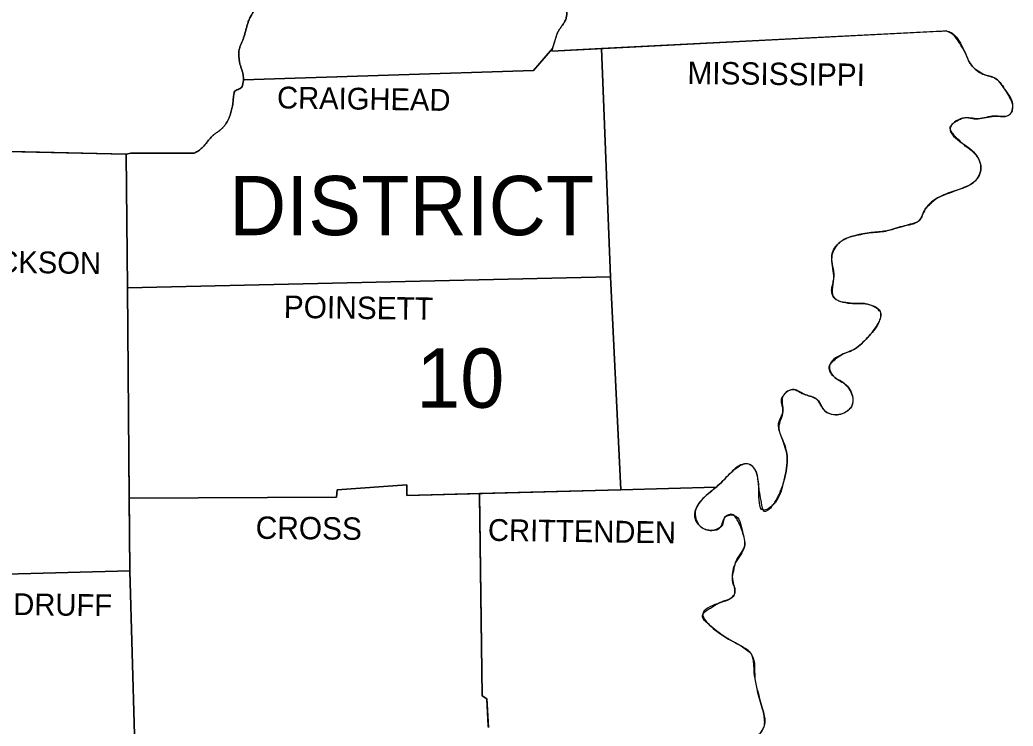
# Model space of a CAD drawing. Extents: x -28335 to 1228743, y -22428 to 152440.
# Drawn here: x 33552 to 37883, y 12977 to 16055 of the extents above; entities that cross this region are included whole.
import ezdxf

# ---------------------------------------------------------------- set-up
doc = ezdxf.new("R2010")
doc.units = 0
doc.layers.add('Level 16', color=7, linetype='Continuous')
doc.layers.add('Level 8', color=7, linetype='Continuous')

msp = doc.modelspace()

# ---------------------------------------------------------------- linework, layer by layer
at = {"layer": 'Level 16'}
for p, q in [((35874.9, 15930.7), (35895.4, 15993.9)), ((35871, 15918.7), (35874.9, 15930.7)), ((36087.9, 15929.9), (35871, 15918.7)), ((36127, 14935.6), (36087.9, 15929.9)), ((34015.7, 15470.2), (34020.8, 14887.6)), ((34020.8, 14887.6), (36127, 14935.6)), ((36127, 14935.6), (34020.8, 14887.6)), ((36173, 14007.6), (36127, 14935.6)), ((34020.8, 14887.6), (34028.8, 13970.5)), ((35556, 13990.7), (35556.1, 13981.9)), ((35556.1, 13981.9), (35556, 13990.7)), ((36173, 14007.6), (36588.4, 14019)), ((34028.8, 13970.5), (34031.6, 13653.5)), ((35556.1, 13981.9), (35567.5, 13109.8)), ((35567.5, 13109.8), (35556.1, 13981.9)), ((34031.6, 13653.5), (34051.1, 12939.8)), ((34051.1, 12939.8), (34031.6, 13653.5)), ((35567.5, 13109.8), (35587.8, 13096.2)), ((35587.8, 13096.2), (35567.5, 13109.8)), ((35587.8, 13096.2), (35594.6, 12978.4)), ((35594.6, 12978.4), (35587.8, 13096.2)), ((35594.6, 12978.4), (35595.1, 12970.9)), ((35595.1, 12970.9), (35594.6, 12978.4))]:
    msp.add_line(p, q, dxfattribs=at)
for points in [[(33330.1, 16791), (33331.6, 16743.3), (33139.1, 16725.2), (33141.3, 16661.7), (33082.4, 16659.5), (33102.8, 15490.6), (34015.7, 15470.2)], [(37590.4, 16007.1), (37575.9, 16006.3), (36087.9, 15929.9)], [(34526.7, 15793.9), (35791.7, 15834.9), (35874.9, 15930.7)], [(35874.9, 15930.7), (35791.7, 15834.9), (34526.7, 15793.9)], [(36087.9, 15929.9), (36127, 14935.6), (36173, 14007.6)], [(33424, 13957), (33435.8, 13637.6), (34031.6, 13653.5), (34028.8, 13970.5), (34020.8, 14887.6), (34015.7, 15470.2), (33512, 15481.5)], [(34015.7, 15470.2), (34036.1, 15474.7), (34312.5, 15474.7)], [(34312.5, 15474.7), (34036.1, 15474.7), (34015.7, 15470.2)], [(34028.8, 13970.5), (34933.2, 13975.2), (34935.4, 14006.9), (35239, 14029.5), (35239, 13981.9), (36173, 14007.6)], [(35556, 13990.7), (35239, 13981.9), (35239, 14029.5), (34935.4, 14006.9), (34933.2, 13975.2), (34028.8, 13970.5)], [(36588.4, 14019), (36173, 14007.6), (35556, 13990.7)], [(36588.4, 14019), (36588.4, 14019)], [(36588.4, 14019), (36588.4, 14019)], [(34031.6, 13653.5), (33435.8, 13637.6), (33424, 13957)]]:
    msp.add_lwpolyline(points, dxfattribs=at)
for points in [[(35895.4, 15993.9), (35898.2, 16002.5), (35906.5, 16016.1), (35915.8, 16029.4), (35924.8, 16042.9), (35932.2, 16056.9), (35936.2, 16073.4), (35937.3, 16091.1), (35938.6, 16108.6), (35943.5, 16124.9), (35955.2, 16143.2), (35969.2, 16160.2), (35983.4, 16177.2), (35995.6, 16195.1), (36002.3, 16210.4), (36007.7, 16226.6), (36013.8, 16242.3), (36022.8, 16256.3), (36077.1, 16317.4), (36117.9, 16362.7), (36130.6, 16375.5), (36144.1, 16387.5), (36157.5, 16399.6), (36170, 16412.6), (36175.1, 16420.1), (36178.5, 16428.5), (36182.4, 16447), (36185.7, 16465.8), (36192.7, 16482.8), (36203.7, 16499.3), (36215.1, 16515.5), (36227.2, 16531.2), (36240.2, 16546.2), (36251.8, 16558.8)], [(34513.6, 15756.7), (34514.1, 15757), (34520.9, 15764.7), (34522.9, 15771.1), (34524.5, 15777.6), (34526.5, 15790.7), (34526.8, 15803.9), (34525.4, 15816.8), (34521.9, 15830.9), (34517.2, 15845), (34512.7, 15859.2), (34509.6, 15873.4), (34507.8, 15887.5), (34506.7, 15901.8), (34507, 15916.1), (34509.6, 15930.1), (34514.2, 15943.8), (34519.6, 15957.3), (34525.1, 15970.8), (34529.9, 15984.4), (34534.6, 16000.2), (34538.9, 16016.1), (34543.3, 16032.1), (34548.1, 16047.9), (34554.9, 16064.1), (34563.6, 16079.7), (34572.4, 16095.3), (34576.2, 16102.7)], [(34576.2, 16102.7), (34572.4, 16095.3), (34563.6, 16079.7), (34554.9, 16064.1), (34548.1, 16047.9), (34543.3, 16032.1), (34538.9, 16016.1), (34534.6, 16000.2), (34529.9, 15984.4), (34525.1, 15970.8), (34519.6, 15957.3), (34514.2, 15943.8), (34509.6, 15930.1), (34507, 15916.1), (34506.7, 15901.8), (34507.8, 15887.5), (34509.6, 15873.4), (34512.7, 15859.2), (34517.2, 15845), (34521.9, 15830.9), (34525.4, 15816.8), (34526.8, 15803.9), (34526.7, 15793.9)], [(37356.2, 15142.3), (37400.1, 15155.3), (37435.5, 15165.7), (37470.3, 15178), (37480.8, 15187.4), (37486.9, 15201.5), (37492, 15216.9), (37499.8, 15230.1), (37514.1, 15245.5), (37529, 15260.6), (37563.2, 15284.5), (37598.2, 15298.3), (37633.4, 15311.6), (37669.8, 15326.1), (37705.9, 15343.4), (37719.9, 15354.7), (37730.5, 15369.4), (37742.1, 15402.3), (37742.8, 15417.6), (37739.9, 15433.6), (37733.5, 15449.3), (37724, 15463.4), (37708.2, 15479.2), (37691.5, 15492.6), (37674.6, 15505.5), (37658.3, 15520), (37627.6, 15550.5), (37615.1, 15566), (37608.5, 15581.2), (37608.3, 15584.6), (37608.9, 15587.9), (37612.3, 15594.6), (37625.6, 15607.3), (37644, 15618.3), (37662.9, 15626.5), (37671.4, 15628.6), (37679.9, 15629.2), (37696.9, 15627.3), (37713.9, 15624.4), (37730.8, 15624.3), (37765.9, 15629.9), (37801, 15635.6), (37816.8, 15635.9), (37832.7, 15634.4), (37848.7, 15634.7), (37864.5, 15640.1), (37867.5, 15642.1), (37870.3, 15644.5), (37875, 15649.9), (37880.9, 15662.9), (37880.3, 15689.9), (37867.8, 15718.4), (37850.9, 15746.6), (37831.2, 15774.6), (37807.8, 15798.7), (37794.7, 15805.9), (37780, 15809.9), (37765.2, 15813.4), (37751.2, 15819.1), (37701.4, 15857.6), (37691.1, 15873.6), (37683.6, 15890.9), (37676.5, 15908.6), (37667.4, 15925.5), (37651.5, 15950.7), (37634.7, 15975.5), (37615, 15995.8), (37590.4, 16007.1)], [(34526.7, 15793.9), (34526.5, 15790.7), (34524.5, 15777.6), (34522.9, 15771.1), (34520.9, 15764.7), (34514.1, 15757), (34513.6, 15756.7)], [(34312.5, 15474.7), (34321.9, 15479.6), (34330.6, 15484.8), (34346.5, 15497.4), (34358.4, 15510.1), (34369.3, 15523.5), (34380.2, 15536.9), (34391.8, 15549.5), (34402.2, 15558.2), (34413.3, 15566.2), (34424.5, 15574.3), (34434.8, 15583.5), (34443.8, 15593.8), (34451.7, 15604.7), (34464.3, 15628.8), (34471.9, 15651.3), (34477.8, 15674.1), (34480.8, 15690.4), (34482.3, 15707), (34483.9, 15723.6), (34485.1, 15731.7), (34486.9, 15739.8), (34493, 15747.5), (34503.5, 15752.2), (34513.6, 15756.7)], [(34513.6, 15756.7), (34503.5, 15752.2), (34493, 15747.5), (34486.9, 15739.8), (34485.1, 15731.7), (34483.9, 15723.6), (34482.3, 15707), (34480.8, 15690.4), (34477.8, 15674.1), (34471.9, 15651.3), (34464.3, 15628.8), (34451.7, 15604.7), (34443.8, 15593.8), (34434.8, 15583.5), (34424.5, 15574.3), (34413.3, 15566.2), (34402.2, 15558.2), (34391.8, 15549.5), (34380.2, 15536.9), (34369.3, 15523.5), (34358.4, 15510.1), (34346.5, 15497.4), (34330.6, 15484.8), (34321.9, 15479.6), (34312.5, 15474.7)], [(36968.6, 14425.1), (36971.9, 14423.7), (37021.8, 14405.5), (37034.7, 14394.6), (37043.6, 14378.8), (37052.4, 14362.2), (37064.8, 14348.9), (37093.8, 14336.3), (37123.7, 14335.3), (37152.6, 14346.5), (37165.9, 14356.3), (37178.1, 14369.3), (37182.6, 14416.9), (37148.6, 14469), (37137.5, 14478), (37125, 14484.8), (37112.5, 14491.7), (37101.1, 14500.7), (37084.5, 14524.3), (37082.9, 14548.3), (37092.5, 14561.7), (37105, 14574.2), (37135, 14595.8), (37149.3, 14602.7), (37163.9, 14608), (37178.2, 14613.4), (37191.7, 14620.7), (37248.3, 14670.6), (37261.7, 14685.6), (37273.8, 14701.3), (37295.9, 14734), (37306.9, 14759), (37307.7, 14772.1), (37302.7, 14783.8), (37296.3, 14790.8), (37289.3, 14796.9), (37273.8, 14806.5), (37239.2, 14817.8), (37222.9, 14819.5), (37206.4, 14819.2), (37189.9, 14818.8), (37173.6, 14820.1), (37152.9, 14822.9), (37132.3, 14826.6), (37113.6, 14834.4), (37098.8, 14849.5), (37095.9, 14855), (37093.9, 14860.5), (37091.9, 14871.5), (37093.9, 14893.6), (37098.9, 14915.8), (37101.1, 14937.9), (37098.9, 14958.8), (37095.7, 14979.8), (37093, 15000.8), (37092, 15021.7), (37094.2, 15037.7), (37100, 15053), (37121.5, 15080.6), (37129.7, 15087.5), (37138.1, 15093.5), (37155.2, 15102.9), (37173, 15109.6), (37191.7, 15114.6), (37227.8, 15122.1), (37264.2, 15128.2), (37280, 15129.8), (37296, 15130.9), (37327.6, 15135), (37356.2, 15142.3)], [(36588.4, 14019), (36602.7, 14031.8), (36654.8, 14083.9), (36677.7, 14102.4), (36690, 14110.4), (36702.4, 14117.9), (36720.4, 14122), (36738.6, 14115.6), (36748.4, 14106.8), (36756.3, 14097.1), (36762.2, 14086.4), (36765.8, 14074.8), (36768.6, 14057.3), (36770.6, 14039.7), (36774.9, 14004.6), (36782.3, 13960.9), (36793, 13918.5), (36796.1, 13914.3), (36801, 13913.5), (36814.1, 13919.3), (36838.3, 13943.4), (36849.8, 13962.7), (36860.3, 13982.1), (36869.4, 14002), (36876.8, 14022.7), (36894.9, 14099.7), (36897.2, 14154.1), (36876.8, 14226.6), (36860.9, 14278.7), (36860.7, 14296.1), (36866.3, 14313.7), (36873.8, 14331.3), (36879.1, 14348.9), (36879.4, 14356.9), (36878.2, 14365.1), (36874.3, 14381.6), (36872.7, 14398.2), (36879.1, 14414.6), (36884.6, 14421.6), (36890.4, 14428), (36902.8, 14438.5), (36928.9, 14444.1), (36948.7, 14435.2), (36968.6, 14425.1)], [(36702.4, 13825.6), (36687.6, 13862.9), (36677.8, 13880.1), (36672.2, 13888.2), (36666.1, 13895.9), (36657.8, 13900.2), (36647.1, 13899.4), (36636.3, 13895.1), (36627.6, 13889.1), (36621.7, 13878.9), (36618.9, 13866.2), (36615.4, 13853.6), (36607.2, 13843.8), (36597.6, 13838.2), (36588, 13833.9), (36578.3, 13831.2), (36568.7, 13830.2), (36556.2, 13830.8), (36543.8, 13833.5), (36531.3, 13839), (36518.9, 13848.3), (36514.8, 13852.3), (36511.1, 13856.5), (36504.8, 13865.2), (36496.7, 13883.4), (36494.7, 13901.7), (36498.5, 13918.5), (36505.7, 13933.4), (36514.5, 13948.1), (36537, 13975.2), (36562.7, 13997.6), (36588.4, 14019)], [(36332.9, 12569.7), (36360.3, 12573.1), (36387.5, 12579.8), (36392.4, 12582.1), (36396.9, 12584.8), (36405.1, 12591.5), (36418.3, 12608.2), (36428.6, 12627.8), (36437.3, 12647.7), (36462.2, 12706.6), (36487.2, 12761), (36521.1, 12824.4), (36555.1, 12887.8), (36574.9, 12914.9), (36602.7, 12933.1), (36609.9, 12935), (36617.2, 12935.8), (36632.2, 12934.9), (36661.6, 12928.6), (36674.1, 12925), (36686.5, 12920.3), (36699, 12915.8), (36711.4, 12912.8), (36723.3, 12912.1), (36735.2, 12914), (36747.1, 12918.7), (36759, 12926.3), (36768, 12933.9), (36776.1, 12941.7), (36789.1, 12958), (36797.2, 12975.5), (36799.8, 12994.3), (36798.8, 13008.5), (36796.9, 13022.7), (36790.7, 13050.9), (36768.1, 13132.5), (36762.1, 13161.9), (36756.7, 13191.4), (36754.1, 13214.5), (36752.9, 13237.9), (36750.9, 13261.2), (36745.4, 13284.3), (36742.4, 13290.9), (36738.2, 13296.7), (36727.6, 13306.7), (36702.4, 13322.8), (36685.4, 13332.7), (36668.3, 13342), (36651.2, 13351.3), (36634.4, 13361.3), (36599.9, 13384.9), (36566.5, 13411.1), (36537.6, 13438.3), (36528.7, 13452.9), (36530.2, 13465.5), (36535.9, 13471.8), (36542.7, 13477.8), (36558.6, 13489.3), (36576.3, 13500.1), (36593.6, 13510.8), (36602.7, 13515.7), (36612.2, 13519.5), (36631.5, 13526), (36650.1, 13534.5), (36666.1, 13549.3), (36668.7, 13553.5), (36670.4, 13557.7), (36671.5, 13566.3), (36667.7, 13584), (36661.4, 13601.9), (36659.3, 13619.5), (36664.7, 13654.7), (36672.9, 13689.7), (36681.4, 13708.1), (36693.1, 13725.2), (36704.4, 13742.1), (36711.4, 13760), (36702.4, 13825.6)]]:
    msp.add_spline(points, degree=3, dxfattribs=at)
at = {"layer": 'Level 8'}
msp.add_line((35871, 15918.7), (35895.4, 15993.9), dxfattribs=at)
for points in [[(32948.3, 17620.6), (32939.7, 17552), (32985, 17545.2), (32982.7, 17518), (33034.8, 17506.7), (33039.4, 17470.4), (33064.3, 17454.6), (33071.1, 17345.8), (33200.2, 17332.2), (33200.2, 17234.8), (33247.8, 17228), (33247.8, 17189.5), (33288.6, 17178.2), (33286.3, 17046.8), (33322.5, 17040), (33331.6, 16743.3), (33139.1, 16725.2), (33141.3, 16661.7), (33082.4, 16659.5), (33102.8, 15490.6), (34015.7, 15470.2), (34031.6, 13653.5), (33435.8, 13637.6), (33424, 13957)], [(35871, 15918.7), (37590.4, 16007.1)], [(34526.7, 15793.9), (35791.7, 15834.9), (35874.9, 15930.7)], [(36087.9, 15929.9), (36127, 14935.6), (36173, 14007.6)], [(34312.5, 15474.7), (34036.1, 15474.7), (34015.7, 15470.2)], [(36127, 14935.6), (34020.8, 14887.6)], [(34028.8, 13970.5), (34933.2, 13975.2), (34935.4, 14006.9), (35239, 14029.5), (35239, 13981.9), (36588.4, 14019)], [(35556, 13990.7), (35567.5, 13109.8), (35587.8, 13096.2), (35595.1, 12970.9)], [(35556.1, 13981.9), (35567.5, 13109.8), (35587.8, 13096.2), (35594.6, 12978.4)], [(35556.1, 13981.9), (35567.5, 13109.8), (35587.8, 13096.2), (35594.6, 12978.4)], [(35556.1, 13981.9), (35567.5, 13109.8), (35587.8, 13096.2), (35594.6, 12978.4)], [(35556.1, 13981.9), (35567.5, 13109.8), (35587.8, 13096.2), (35594.6, 12978.4)], [(34031.6, 13653.5), (34065.6, 12412.1), (33526.4, 12409.9), (33524.2, 12360), (33367.8, 12351), (33354.3, 12092.7), (33139.4, 12092.7)]]:
    msp.add_lwpolyline(points, dxfattribs=at)
for points in [[(36414.7, 17687.9), (36416.6, 17662.9), (36419.2, 17637.9), (36422.4, 17613.1), (36426, 17588.2), (36431.3, 17574.2), (36440.5, 17561.5), (36450.3, 17549.2), (36457.7, 17536.1), (36460.6, 17513.1), (36457.8, 17488.3), (36456, 17463.7), (36457.7, 17452), (36462.2, 17441), (36479.5, 17418.7), (36500.8, 17400.2), (36517, 17389.4), (36533.7, 17379.9), (36550.4, 17370.4), (36566.5, 17359.4), (36599.1, 17330.4), (36613.1, 17313.5), (36619.5, 17304), (36625.3, 17293.7), (36633.5, 17274.6), (36638.3, 17255.2), (36640, 17235.9), (36638.9, 17216.7), (36635, 17196.9), (36629.4, 17177.2), (36624.1, 17157.4), (36620.8, 17137.4), (36619.6, 17115.4), (36618.8, 17093.3), (36617.9, 17071.2), (36616.3, 17049.1), (36607.2, 16972.1), (36603, 16936.6), (36599.5, 16919.1), (36596.9, 16910.4), (36593.6, 16901.8), (36570, 16870.5), (36539.3, 16845.2), (36526.3, 16834.9), (36513.1, 16825), (36499.9, 16814.9), (36487.2, 16804.4), (36439.6, 16756.9), (36430.7, 16744.7), (36423, 16731.5), (36415.2, 16718.6), (36405.6, 16707), (36346.7, 16652.7), (36287.8, 16596), (36240.2, 16546.2), (36227.2, 16531.2), (36215.1, 16515.5), (36203.7, 16499.3), (36192.7, 16482.8), (36185.7, 16465.8), (36182.4, 16447), (36178.5, 16428.5), (36175.1, 16420.1), (36170, 16412.6), (36157.5, 16399.6), (36144.1, 16387.5), (36130.6, 16375.5), (36117.9, 16362.7), (36077.1, 16317.4), (36022.8, 16256.3), (36013.8, 16242.3), (36007.7, 16226.6), (36002.3, 16210.4), (35995.6, 16195.1), (35983.4, 16177.2), (35969.2, 16160.2), (35955.2, 16143.2), (35943.5, 16124.9), (35938.6, 16108.6), (35937.3, 16091.1), (35936.2, 16073.4), (35932.2, 16056.9), (35924.8, 16042.9), (35915.8, 16029.4), (35906.5, 16016.1), (35898.2, 16002.5), (35895.4, 15993.9)], [(34744.4, 16421.4), (34725.3, 16393.9), (34708.9, 16365), (34701.8, 16349.2), (34695.8, 16333), (34689.5, 16316.9), (34681.7, 16301.6), (34669, 16282.9), (34655.1, 16265.1), (34640.8, 16247.4), (34627.4, 16229.1), (34605.4, 16194.8), (34595.5, 16177.1), (34586.6, 16158.8), (34583.5, 16147.3), (34582.8, 16135.1), (34582.3, 16122.9), (34579.8, 16111.3), (34572.4, 16095.3), (34563.6, 16079.7), (34554.9, 16064.1), (34548.1, 16047.9), (34543.3, 16032.1), (34538.9, 16016.1), (34534.6, 16000.2), (34529.9, 15984.4), (34525.1, 15970.8), (34519.6, 15957.3), (34514.2, 15943.8), (34509.6, 15930.1), (34507, 15916.1), (34506.7, 15901.8), (34507.8, 15887.5), (34509.6, 15873.4), (34512.7, 15859.2), (34517.2, 15845), (34521.9, 15830.9), (34525.4, 15816.8), (34526.8, 15803.9), (34526.5, 15790.7), (34524.5, 15777.6), (34522.9, 15771.1), (34520.9, 15764.7), (34514.1, 15757), (34503.5, 15752.2), (34493, 15747.5), (34486.9, 15739.8), (34485.1, 15731.7), (34483.9, 15723.6), (34482.3, 15707), (34480.8, 15690.4), (34477.8, 15674.1), (34471.9, 15651.3), (34464.3, 15628.8), (34451.7, 15604.7), (34443.8, 15593.8), (34434.8, 15583.5), (34424.5, 15574.3), (34413.3, 15566.2), (34402.2, 15558.2), (34391.8, 15549.5), (34380.2, 15536.9), (34369.3, 15523.5), (34358.4, 15510.1), (34346.5, 15497.4), (34330.6, 15484.8), (34321.9, 15479.6), (34312.5, 15474.7)], [(37565.5, 16004.8), (37590.4, 16007.1), (37667.4, 15925.5), (37701.4, 15857.6), (37751.2, 15819.1), (37807.8, 15798.7), (37850.9, 15746.6), (37880.3, 15689.9), (37864.5, 15640.1), (37801, 15635.6), (37730.8, 15624.3), (37662.9, 15626.5), (37608.5, 15581.2), (37658.3, 15520), (37724, 15463.4), (37742.1, 15402.3), (37705.9, 15343.4), (37633.4, 15311.6), (37563.2, 15284.5), (37499.8, 15230.1), (37470.3, 15178), (37400.1, 15155.3), (37327.6, 15135), (37264.2, 15128.2), (37191.7, 15114.6), (37121.5, 15080.6), (37092, 15021.7), (37101.1, 14937.9), (37098.8, 14849.5), (37173.6, 14820.1), (37239.2, 14817.8), (37302.7, 14783.8), (37295.9, 14734), (37248.3, 14670.6), (37191.7, 14620.7), (37135, 14595.8), (37082.9, 14548.3), (37101.1, 14500.7), (37148.6, 14469), (37182.6, 14416.9), (37178.1, 14369.3), (37123.7, 14335.3), (37064.8, 14348.9), (37021.8, 14405.5), (36971.9, 14423.7), (36928.9, 14444.1), (36879.1, 14414.6), (36879.1, 14348.9), (36860.9, 14278.7), (36876.8, 14226.6), (36897.2, 14154.1), (36894.9, 14099.7), (36876.8, 14022.7), (36838.3, 13943.4), (36793, 13918.5), (36774.9, 14004.6), (36765.8, 14074.8), (36738.6, 14115.6), (36702.4, 14117.9), (36654.8, 14083.9), (36602.7, 14031.8), (36537, 13975.2), (36498.5, 13918.5), (36518.9, 13848.3), (36568.7, 13830.2), (36607.2, 13843.8), (36627.6, 13889.1), (36666.1, 13895.9), (36702.4, 13825.6)], [(36702.4, 13825.6), (36711.4, 13760), (36672.9, 13689.7), (36659.3, 13619.5), (36666.1, 13549.3), (36593.6, 13510.8), (36530.2, 13465.5), (36566.5, 13411.1), (36634.4, 13361.3), (36702.4, 13322.8), (36745.4, 13284.3), (36756.7, 13191.4), (36768.1, 13132.5), (36790.7, 13050.9), (36799.8, 12994.3), (36759, 12926.3), (36711.4, 12912.8), (36661.6, 12928.6), (36602.7, 12933.1), (36555.1, 12887.8), (36521.1, 12824.4), (36487.2, 12761), (36462.2, 12706.6), (36437.3, 12647.7), (36387.5, 12579.8), (36326.3, 12568.4), (36253.8, 12550.3), (36210.8, 12500.5), (36217.6, 12416.7), (36258.4, 12360), (36290.1, 12289.8), (36312.7, 12228.6), (36301.4, 12151.6), (36269.7, 12095), (36228.9, 12061), (36210.8, 11988.5), (36181.4, 11934.2), (36154.2, 11916), (36099.8, 11920.6), (36040.9, 11931.9), (35991.1, 11927.4), (35943.5, 11902.5), (35895.9, 11918.3), (35846.1, 11972.7), (35805.3, 12013.4), (35760, 12029.3), (35712.4, 12004.4), (35703.4, 11929.6), (35726, 11852.6), (35746.4, 11748.4), (35726, 11685), (35719.2, 11580.8)]]:
    msp.add_spline(points, degree=3, dxfattribs=at)

# ---------------------------------------------------------------- texts
for s, height, rotation, p in [('MISSISSIPPI', 97.394, 359.3097, (36462.2, 15776)), ('CRAIGHEAD', 95.15, 359.1159, (34672.7, 15669.6)), ('JACKSON', 95.12, 359.1352, (33304.4, 14956)), ('POINSETT', 97.4, 359.1987, (34702.1, 14756.7)), ('CROSS', 97.4, 359.384, (34579.8, 13793.9)), ('CRITTENDEN', 95.15, 359.213, (35592.4, 13784.9)), ('WOODRUFF', 95.12, 359.2748, (33204.7, 13465.5))]:
    msp.add_text(s, height=height, rotation=rotation, dxfattribs=at).set_placement(p)
for s, p in [('DISTRICT', (34464.3, 15116.8)), ('10', (35280.4, 14364.8))]:
    msp.add_text(s, height=258.24, dxfattribs=at).set_placement(p)

doc.saveas('drawing.dxf')
